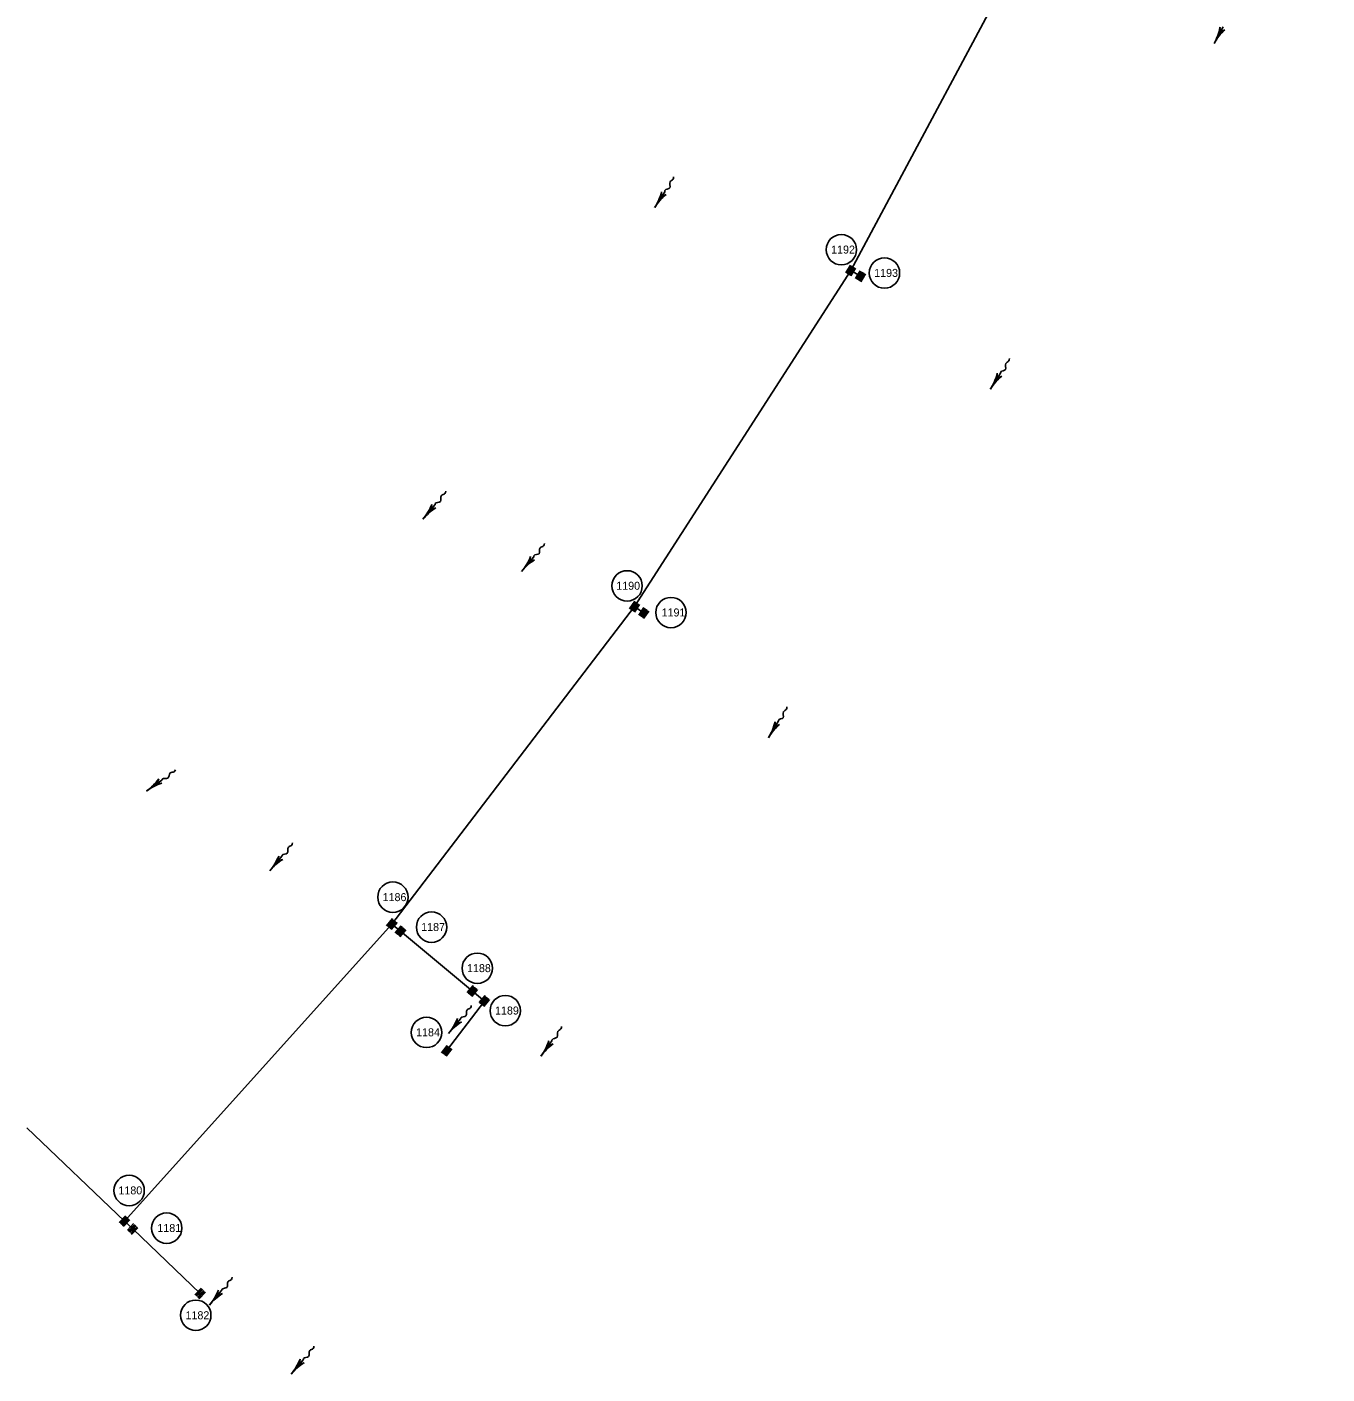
# Model space of a CAD drawing. Extents: x 594534 to 598564, y 225861 to 236229.
# Drawn here: x 597271 to 598246, y 231566 to 232575 of the extents above; entities that cross this region are included whole.
import ezdxf

# ---------------------------------------------------------------- set-up
doc = ezdxf.new("R2010")
doc.units = 0
for name, color, linetype in [('P_DRN_Flow', 7, 'Continuous'), ('P_DRN_Inlet', 7, 'Continuous'), ('P_DRN_SS_UG', 7, 'Continuous'), ('P_DRN_Text', 7, 'Continuous')]:
    doc.layers.add(name, color=color, linetype=linetype)

msp = doc.modelspace()

# ---------------------------------------------------------------- linework, layer by layer
at = {"layer": 'P_DRN_Flow'}
for p, q in [((598161.1, 232563.1), (598167.8, 232575.5)), ((597741.5, 232440.1), (597749.1, 232452)), ((597993.2, 232303.9), (598000.8, 232315.9)), ((597567.7, 232206.5), (597576.8, 232217.4)), ((597641.7, 232167.4), (597650.8, 232178.3)), ((597826.9, 232042.7), (597834.2, 232054.8)), ((597360.4, 232002.7), (597371.9, 232011)), ((597452.9, 231943), (597462, 231953.8)), ((597586.9, 231821.1), (597596, 231831.9)), ((597656.2, 231804), (597664.4, 231815.5)), ((597407.6, 231617.5), (597416.7, 231628.3)), ((597468.9, 231565.7), (597478, 231576.5))]:
    msp.add_line(p, q, dxfattribs=at)
for points in [[(598165.4, 232575.3), (598165.7, 232571.5), (598169, 232573.4)], [(597746.7, 232452), (597746.7, 232448.2), (597750.1, 232449.9)], [(597998.4, 232315.8), (597998.4, 232312), (598001.8, 232313.7)], [(597574.4, 232217.6), (597573.9, 232213.9), (597577.4, 232215.1)], [(597648.4, 232178.5), (597647.9, 232174.8), (597651.5, 232176)], [(597831.8, 232054.7), (597831.8, 232050.9), (597835.2, 232052.6)], [(597369.6, 232011.8), (597368.2, 232008.3), (597372, 232008.6)], [(597459.6, 231954), (597459, 231950.3), (597462.6, 231951.5)], [(597593.6, 231832.2), (597593, 231828.4), (597596.6, 231829.6)], [(597662, 231815.6), (597661.8, 231811.8), (597665.3, 231813.3)], [(597414.3, 231628.6), (597413.8, 231624.8), (597417.4, 231626)], [(597475.6, 231576.8), (597475.1, 231573.1), (597478.6, 231574.2)]]:
    msp.add_lwpolyline(points, dxfattribs=at)
for centre, start, end in [((598124.2, 232583.2), 331.3524, 349.1147), ((598197.9, 232543), 133.5901, 151.3524), ((597706.1, 232462.6), 327.5498, 345.3121), ((597776.9, 232417.6), 129.7875, 147.5498), ((597957.8, 232326.5), 327.5383, 345.3006), ((598028.6, 232281.4), 129.776, 147.5383), ((597535.5, 232233.5), 320.0425, 337.8048), ((597599.9, 232179.6), 122.2801, 140.0425), ((597609.6, 232194.4), 320.0425, 337.8048), ((597673.9, 232140.5), 122.2801, 140.0425), ((597791, 232064.5), 328.6698, 346.4321), ((597862.7, 232020.9), 130.9075, 148.6698), ((597335.9, 232036.8), 305.7197, 323.4821), ((597384.9, 231968.7), 107.9574, 125.7197), ((597420.7, 231969.9), 320.0425, 337.8048), ((597485, 231916), 122.2801, 140.0425), ((597554.7, 231848), 320.0425, 337.8048), ((597619, 231794.1), 122.2801, 140.0425), ((597622.1, 231828.4), 324.4559, 342.2182), ((597690.4, 231779.6), 126.6935, 144.4559), ((597375.5, 231644.4), 320.0425, 337.8048), ((597439.8, 231590.5), 122.2801, 140.0425), ((597436.7, 231592.7), 320.0425, 337.8048), ((597501.1, 231538.8), 122.2801, 140.0425)]:
    msp.add_arc(centre, 42, start, end, dxfattribs=at)
for points in [[(597749.1, 232452), (597749.2, 232452.9), (597752.8, 232454.9), (597753, 232459.4), (597755.3, 232461.3), (597755.7, 232463.1)], [(598000.8, 232315.9), (598001, 232316.7), (598004.5, 232318.7), (598004.8, 232323.2), (598007.1, 232325.1), (598007.5, 232326.9)], [(597576.8, 232217.4), (597577, 232218.2), (597580.8, 232219.7), (597581.6, 232224.2), (597584.2, 232225.7), (597584.8, 232227.4)], [(597650.8, 232178.3), (597651, 232179.1), (597654.8, 232180.6), (597655.6, 232185), (597658.2, 232186.6), (597658.8, 232188.3)], [(597834.2, 232054.8), (597834.3, 232055.6), (597837.8, 232057.7), (597838, 232062.2), (597840.3, 232064.1), (597840.6, 232065.9)], [(597371.9, 232011), (597372.3, 232011.7), (597376.4, 232012.3), (597378.3, 232016.3), (597381.1, 232017.2), (597382.1, 232018.7)], [(597462, 231953.8), (597462.2, 231954.6), (597466, 231956.1), (597466.8, 231960.6), (597469.3, 231962.1), (597470, 231963.9)], [(597596, 231831.9), (597596.2, 231832.7), (597600, 231834.3), (597600.8, 231838.7), (597603.4, 231840.2), (597604, 231842)], [(597664.4, 231815.5), (597664.6, 231816.3), (597668.3, 231818.2), (597668.8, 231822.6), (597671.2, 231824.4), (597671.7, 231826.2)], [(597416.7, 231628.3), (597417, 231629.1), (597420.7, 231630.7), (597421.6, 231635.1), (597424.1, 231636.6), (597424.7, 231638.4)], [(597478, 231576.5), (597478.2, 231577.3), (597482, 231578.9), (597482.8, 231583.3), (597485.4, 231584.9), (597486, 231586.6)]]:
    msp.add_spline(points, degree=3, dxfattribs=at)
at = {"layer": 'P_DRN_Inlet'}
for p, q in [((597884.8, 232391.1), (597888.3, 232397)), ((597885.6, 232390.6), (597889.1, 232396.5)), ((597886.4, 232390.2), (597889.9, 232396.1)), ((597887.1, 232389.7), (597890.6, 232395.6)), ((597887.9, 232389.2), (597891.4, 232395.2)), ((597888.7, 232388.8), (597892.2, 232394.7)), ((597892.1, 232386.8), (597895.6, 232392.7)), ((597892.9, 232386.3), (597896.4, 232392.2)), ((597893.7, 232385.8), (597897.2, 232391.8)), ((597894.5, 232385.4), (597898, 232391.3)), ((597895.2, 232384.9), (597898.7, 232390.8)), ((597896, 232384.5), (597899.5, 232390.4)), ((597722.6, 232139.4), (597726.5, 232145.1)), ((597723.3, 232138.9), (597727.2, 232144.6)), ((597724.1, 232138.4), (597728, 232144.1)), ((597724.8, 232137.9), (597728.7, 232143.5)), ((597725.5, 232137.4), (597729.4, 232143)), ((597726.3, 232136.9), (597730.2, 232142.5)), ((597729.5, 232134.5), (597733.4, 232140.2)), ((597730.3, 232134), (597734.2, 232139.7)), ((597731, 232133.5), (597734.9, 232139.2)), ((597731.8, 232133), (597735.7, 232138.7)), ((597732.5, 232132.5), (597736.4, 232138.1)), ((597733.2, 232132), (597737.1, 232137.6)), ((597540.5, 231901.8), (597544.8, 231907.1)), ((597541.2, 231901.2), (597545.5, 231906.5)), ((597541.9, 231900.7), (597546.2, 231906)), ((597542.5, 231900.1), (597546.9, 231905.4)), ((597543.2, 231899.5), (597547.6, 231904.8)), ((597543.9, 231898.9), (597548.3, 231904.2)), ((597547, 231896.4), (597551.4, 231901.7)), ((597547.7, 231895.8), (597552.1, 231901.1)), ((597548.4, 231895.2), (597552.8, 231900.5)), ((597549.1, 231894.6), (597553.5, 231899.9)), ((597549.8, 231894.1), (597554.2, 231899.4)), ((597550.5, 231893.5), (597554.9, 231898.8)), ((597600.8, 231851.7), (597605.3, 231856.9)), ((597601.5, 231851.1), (597605.9, 231856.3)), ((597602.2, 231850.5), (597606.6, 231855.8)), ((597602.9, 231849.9), (597607.3, 231855.2)), ((597603.6, 231849.3), (597608, 231854.6)), ((597604.3, 231848.8), (597608.7, 231854)), ((597609.9, 231844.2), (597614.3, 231849.4)), ((597610.5, 231843.6), (597615, 231848.8)), ((597611.2, 231843), (597615.7, 231848.2)), ((597611.9, 231842.4), (597616.4, 231847.7)), ((597612.6, 231841.8), (597617, 231847.1)), ((597613.3, 231841.2), (597617.7, 231846.5)), ((597581.7, 231806.6), (597585.8, 231812.1)), ((597582.4, 231806.1), (597586.6, 231811.6)), ((597583.1, 231805.5), (597587.3, 231811)), ((597583.8, 231805), (597588, 231810.5)), ((597584.5, 231804.4), (597588.7, 231809.9)), ((597585.2, 231803.9), (597589.4, 231809.4)), ((597339.9, 231679.4), (597344.6, 231684.4)), ((597340.6, 231678.8), (597345.3, 231683.8)), ((597341.2, 231678.1), (597345.9, 231683.2)), ((597341.9, 231677.5), (597346.6, 231682.5)), ((597342.5, 231676.9), (597347.2, 231681.9)), ((597343.2, 231676.3), (597347.9, 231681.3)), ((597346.1, 231673.5), (597350.8, 231678.5)), ((597346.7, 231672.9), (597351.4, 231677.9)), ((597347.4, 231672.3), (597352.1, 231677.3)), ((597348, 231671.7), (597352.7, 231676.7)), ((597348.7, 231671), (597353.4, 231676.1)), ((597349.3, 231670.4), (597354, 231675.4)), ((597396.7, 231625.2), (597401.4, 231630.2)), ((597397.4, 231624.6), (597402.1, 231629.6)), ((597398, 231624), (597402.7, 231629)), ((597398.7, 231623.3), (597403.4, 231628.4)), ((597399.3, 231622.7), (597404, 231627.7)), ((597400, 231622.1), (597404.7, 231627.1))]:
    msp.add_line(p, q, dxfattribs=at)
for points in [[(597888.9, 232391.5), (597889.9, 232393.2), (597888.2, 232394.3), (597887.1, 232392.5)], [(597896.2, 232387.2), (597897.2, 232388.9), (597895.5, 232389.9), (597894.5, 232388.2)], [(597726.6, 232139.6), (597727.8, 232141.2), (597726.1, 232142.4), (597725, 232140.7)], [(597733.6, 232134.7), (597734.7, 232136.3), (597733.1, 232137.5), (597731.9, 232135.8)], [(597544.5, 231901.6), (597545.8, 231903.1), (597544.3, 231904.4), (597543, 231902.9)], [(597551.1, 231896.2), (597552.3, 231897.7), (597550.8, 231899), (597549.5, 231897.4)], [(597604.9, 231851.4), (597606.2, 231853), (597604.6, 231854.2), (597603.4, 231852.7)], [(597613.9, 231843.9), (597615.2, 231845.4), (597613.7, 231846.7), (597612.4, 231845.2)], [(597585.7, 231806.6), (597586.9, 231808.2), (597585.4, 231809.4), (597584.1, 231807.8)], [(597343.9, 231678.9), (597345.3, 231680.4), (597343.9, 231681.7), (597342.5, 231680.3)], [(597350.1, 231673.1), (597351.5, 231674.5), (597350, 231675.9), (597348.6, 231674.4)], [(597400.8, 231624.7), (597402.1, 231626.2), (597400.7, 231627.6), (597399.3, 231626.1)]]:
    msp.add_lwpolyline(points, close=True, dxfattribs=at)
at = {"layer": 'P_DRN_SS_UG'}
for p, q in [((597613.8, 231845.3), (597604.8, 231852.8)), ((597343.9, 231680.3), (597270.8, 231750.3)), ((597350.1, 231674.5), (597343.9, 231680.3)), ((597400.7, 231626.2), (597350.1, 231674.5))]:
    msp.add_line(p, q, dxfattribs=at)
for points in [[(598245.7, 233215.4), (598149, 232931.9), (598029.7, 232657.1), (597888.5, 232392.9), (597726.4, 232141), (597544.4, 231903), (597343.9, 231680.3)], [(597888.5, 232392.9), (597895.8, 232388.6)], [(597726.4, 232141), (597733.3, 232136.1)], [(597604.8, 231852.8), (597550.9, 231897.6), (597544.4, 231903)], [(597585.5, 231808), (597613.8, 231845.3)], [(597350.1, 231674.5), (597343.9, 231680.3)]]:
    msp.add_lwpolyline(points, dxfattribs=at)
at = {"layer": 'P_DRN_Text'}
for centre in [(597881.5, 232408.5), (597913.8, 232391), (597720.8, 232156.5), (597753.7, 232136.5), (597545.2, 231923.2), (597574.2, 231900.7), (597608.5, 231869.9), (597629.5, 231838.1), (597570.4, 231821.8), (597347.4, 231703.3), (597375.6, 231675.1), (597397.4, 231609.8)]:
    msp.add_circle(centre, 11.4, dxfattribs=at)

# ---------------------------------------------------------------- texts
for s, p in [('1192', (597873.8, 232405.6)), ('1193', (597906.1, 232388.1)), ('1190', (597712.7, 232153.6)), ('1191', (597746.7, 232133.6)), ('1186', (597537.5, 231920.2)), ('1187', (597566.4, 231897.8)), ('1188', (597600.8, 231867)), ('1189', (597621.8, 231835.2)), ('1184', (597562.6, 231818.9)), ('1180', (597339.4, 231700.4)), ('1181', (597368.6, 231672.2)), ('1182', (597389.7, 231606.8))]:
    msp.add_text(s, height=6, dxfattribs=at).set_placement(p)

doc.saveas('drawing.dxf')
